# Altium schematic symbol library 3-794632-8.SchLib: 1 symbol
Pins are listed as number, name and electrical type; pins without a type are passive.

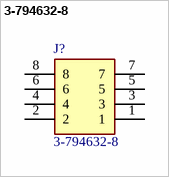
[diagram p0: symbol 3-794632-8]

## 3-794632-8
designator J?
Rectangular Power Connectors, Header, Plug, Wire-to-Board, 8 Position, 3 mm [.118 in] Centerline, Printed Circuit Board, UL 94V-0, Micro MATE-N-LOK; Manufacturer_Name: TE Connectivity; Geometry.Height: 9.44mm
footprint 37946328
pins: 1, 2, 3, 4, 5, 6, 7, 8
